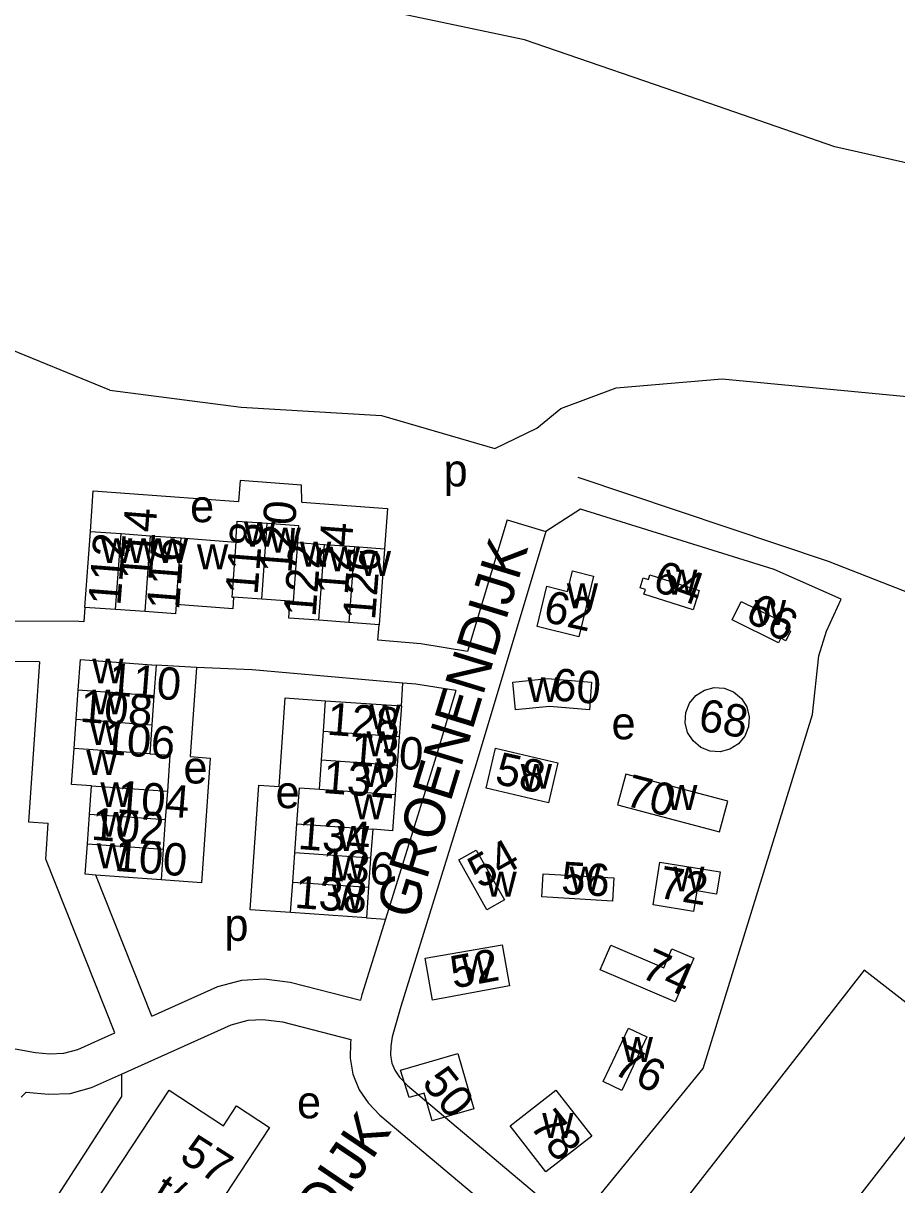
# Model space of a CAD drawing. Extents: x 159441 to 162086, y 388175 to 389787.
# Drawn here: x 160153.1 to 160261, y 389425.1 to 389568.6 of the extents above; entities that cross this region are included whole.
import ezdxf

# ---------------------------------------------------------------- set-up
doc = ezdxf.new("R2010")
doc.units = 0
for name, color, linetype in [('BLT_Basislijn', 7, 'Continuous'), ('BLT_Bebouwing', 7, 'Continuous'), ('BLT_Centroide', 7, 'Continuous'), ('BLT_Huisnummer', 7, 'Continuous'), ('BLT_Huisnummer_ tussenligend', 7, 'Continuous'), ('BLT_Huisnummer_zonder_bebouwing', 7, 'Continuous'), ('BLT_Onderverdeling_panden', 7, 'Continuous'), ('BLT_Plantopo', 7, 'Continuous'), ('BLT_Straatnaam', 7, 'Continuous')]:
    doc.layers.add(name, color=color, linetype=linetype)

msp = doc.modelspace()

# ---------------------------------------------------------------- linework, layer by layer
at = {"layer": 'BLT_Basislijn'}
for p, q in [((160163.8, 389523.25), (160141.73, 389532.25)), ((160212.87, 389507.2), (160207.99, 389490.96)), ((160212.87, 389507.2), (160217.66, 389505.76)), ((160174.51, 389489), (160169.52, 389489.28)), ((160174.51, 389489), (160173.72, 389477.98)), ((160199.8, 389484.24), (160200, 389487.06)), ((160155.87, 389465.33), (160156.18, 389469.75)), ((160164.41, 389443.88), (160155.87, 389465.33)), ((160168.97, 389445.93), (160162.04, 389463.35)), ((160195.5, 389458.06), (160197.84, 389457.9))]:
    msp.add_line(p, q, dxfattribs=at)
for points in [[(160371.16, 389573.06), (160363.22, 389567.72), (160358.94, 389565.1), (160350.1, 389560.99), (160341.38, 389557.76), (160340.2, 389558.69), (160327.39, 389554.65), (160307.62, 389550.59), (160288, 389549.69), (160272.71, 389550.9), (160270.1, 389550.9), (160268.89, 389549.78), (160253.35, 389553.3), (160237.78, 389558.66), (160215.01, 389566.48), (160191.12, 389571.55)], [(160163.8, 389523.25), (160180, 389521.15), (160197.35, 389520.11), (160211.37, 389516.04), (160216.55, 389518.54), (160219.5, 389520.97), (160226.34, 389523.51), (160239.42, 389524.63)], [(160239.42, 389524.63), (160266.58, 389522.05), (160272.05, 389521.43)], [(160187.5, 389509.4), (160187.46, 389511.52), (160187.46, 389511.52), (160179.89, 389512.06), (160179.7, 389509.47)], [(160268.48, 389495.85), (160268.48, 389495.85), (160252.56, 389502.07), (160221.63, 389512.44)], [(160161.38, 389505.79), (160161.74, 389510.79), (160179.7, 389509.47)], [(160187.5, 389509.4), (160198.09, 389508.62), (160197.73, 389503.63)], [(160252.31, 389493.46), (160252.31, 389493.46), (160254.16, 389497.44), (160245.85, 389501.09), (160221.95, 389508.55), (160217.66, 389505.76)], [(160217.66, 389505.76), (160209.05, 389477.09), (160199.72, 389447.12), (160198.67, 389443.39), (160198.5, 389442.22), (160198.48, 389441.1), (160198.63, 389440.12), (160198.99, 389439.26), (160199.59, 389438.41), (160200.58, 389437.37), (160221.21, 389420)], [(160160.69, 389496.41), (160160.56, 389494.64), (160159.96, 389494.67), (160145.91, 389494.71), (160136.49, 389494.39)], [(160207.99, 389490.96), (160202.22, 389491.89), (160196.91, 389492.35), (160197.05, 389494.26)], [(160221.21, 389420), (160237.09, 389439.47), (160250.58, 389483.19), (160251.38, 389490.44), (160252.31, 389493.46)], [(160155.11, 389489.68), (160145.98, 389489.71), (160136.48, 389489.38)], [(160155.11, 389489.68), (160153.72, 389469.93), (160156.18, 389469.75)], [(160200, 389487.06), (160181.35, 389488.69), (160174.51, 389489)], [(160206.54, 389486.13), (160201.6, 389486.92), (160200, 389487.06)], [(160184.69, 389474.29), (160185.45, 389485.22), (160190.44, 389484.88)], [(160206.54, 389486.13), (160204.26, 389478.55), (160197.84, 389457.9)], [(160173.72, 389477.98), (160176.2, 389477.8), (160175.1, 389462.41), (160170.11, 389462.77)], [(160186.12, 389458.71), (160181.13, 389459.05), (160182.21, 389474.46), (160184.69, 389474.29)], [(160197.84, 389457.9), (160194.93, 389448.54), (160194.74, 389447.89)], [(160241.32, 389404.38), (160270.16, 389441.35), (160257, 389451.61), (160228.13, 389414.61)], [(160168.97, 389445.93), (160177.12, 389449.6), (160180.1, 389450.38), (160182.86, 389450.55), (160186.06, 389450.13), (160194.74, 389447.89)], [(160165.21, 389438.76), (160178.79, 389444.87), (160180.89, 389445.41), (160182.69, 389445.53), (160185.11, 389445.21), (160193.56, 389443.03)], [(160151.2, 389442.05), (160154.59, 389441.45), (160156.33, 389441.28), (160158.12, 389441.35), (160159.83, 389441.82), (160164.41, 389443.88)], [(160193.56, 389443.03), (160193.5, 389442.63), (160193.47, 389440.74), (160193.79, 389438.75), (160194.58, 389436.84), (160195.71, 389435.23), (160197.16, 389433.71), (160218.41, 389415.82)], [(160165.21, 389438.76), (160165.21, 389436.02), (160151.05, 389414.07), (160139.58, 389381.2)], [(160152.84, 389435.93), (160153.45, 389436.54), (160156.19, 389436.27), (160158.9, 389436.38), (160161.53, 389437.1), (160165.21, 389438.76)]]:
    msp.add_lwpolyline(points, dxfattribs=at)
at = {"layer": 'BLT_Bebouwing'}
for p, q in [((160160.69, 389496.41), (160161.38, 389505.79)), ((160161.38, 389505.79), (160165.17, 389505.52)), ((160165.17, 389505.52), (160168.76, 389505.26)), ((160161.3, 389504.74), (160161.32, 389504.96)), ((160168.76, 389505.26), (160172.6, 389504.98)), ((160172.6, 389504.98), (160179.34, 389504.46)), ((160186.96, 389504.43), (160190.29, 389504.18)), ((160190.29, 389504.18), (160194.03, 389503.91)), ((160194.03, 389503.91), (160197.73, 389503.63)), ((160197.73, 389503.63), (160197.05, 389494.26)), ((160182.56, 389497.43), (160179.08, 389497.68)), ((160186.04, 389497.18), (160182.56, 389497.43)), ((160164.5, 389496.14), (160160.69, 389496.41)), ((160168.09, 389495.88), (160164.5, 389496.14)), ((160193.33, 389494.54), (160189.61, 389494.81)), ((160197.05, 389494.26), (160193.33, 389494.54)), ((160159.88, 389486.18), (160160.15, 389489.96)), ((160169.52, 389489.28), (160169.24, 389485.49)), ((160159.63, 389482.59), (160159.88, 389486.18)), ((160169.24, 389485.49), (160168.99, 389481.9)), ((160190.18, 389481.11), (160190.44, 389484.88)), ((160190.44, 389484.88), (160199.8, 389484.24)), ((160199.8, 389484.24), (160199.53, 389480.46)), ((160159.38, 389479), (160159.63, 389482.59)), ((160168.99, 389481.9), (160168.73, 389478.34)), ((160189.93, 389477.52), (160190.18, 389481.11)), ((160199.53, 389480.46), (160199.27, 389476.87)), ((160189.68, 389473.94), (160189.93, 389477.52)), ((160199.27, 389476.87), (160199.02, 389473.28)), ((160161.27, 389470.81), (160161.52, 389474.36)), ((160170.9, 389473.69), (160170.64, 389470.15)), ((160161.01, 389467.22), (160161.27, 389470.81)), ((160170.64, 389470.15), (160170.39, 389466.55)), ((160186.63, 389466.08), (160186.88, 389469.66)), ((160196.27, 389469.01), (160196.01, 389465.43)), ((160160.74, 389463.44), (160161.01, 389467.22)), ((160170.39, 389466.55), (160170.11, 389462.77)), ((160186.38, 389462.49), (160186.63, 389466.08)), ((160196.01, 389465.43), (160195.76, 389461.84)), ((160162.04, 389463.35), (160160.74, 389463.44)), ((160170.11, 389462.77), (160162.04, 389463.35)), ((160186.12, 389458.71), (160186.38, 389462.49)), ((160195.76, 389461.84), (160195.5, 389458.06)), ((160195.5, 389458.06), (160186.12, 389458.71))]:
    msp.add_line(p, q, dxfattribs=at)
for points in [[(160179.34, 389504.46), (160179.53, 389507.07), (160183.23, 389506.81)], [(160183.23, 389506.81), (160187.11, 389506.53), (160186.96, 389504.43)], [(160171.97, 389496.77), (160171.88, 389495.61), (160168.09, 389495.88)], [(160179.08, 389497.68), (160178.98, 389496.23), (160171.97, 389496.77)], [(160189.61, 389494.81), (160185.89, 389495.08), (160186.04, 389497.18)], [(160160.15, 389489.96), (160169.52, 389489.28)], [(160161.52, 389474.36), (160159.06, 389474.55), (160159.38, 389479)], [(160168.73, 389478.34), (160171.21, 389478.16), (160170.9, 389473.69)], [(160186.88, 389469.66), (160187.2, 389474.11), (160189.68, 389473.94)], [(160199.02, 389473.28), (160198.7, 389468.83), (160196.27, 389469.01)]]:
    msp.add_lwpolyline(points, dxfattribs=at)
for points in [[(160220.93, 389500.93), (160223.55, 389500.27), (160221.73, 389492.79), (160216.58, 389494.05), (160217.77, 389499.01), (160220.31, 389498.39)], [(160235.85, 389496.1), (160229.76, 389498.03), (160229.95, 389498.62), (160229.29, 389498.83), (160229.67, 389500.04), (160230.33, 389499.84), (160230.52, 389500.43), (160236.61, 389498.5)], [(160247.53, 389494.32), (160247.26, 389493.77), (160247.89, 389493.47), (160247.31, 389492.28), (160246.68, 389492.59), (160246.41, 389492.03), (160240.66, 389494.87), (160241.79, 389497.15)], [(160213.57, 389487.19), (160217.85, 389487.61), (160223.3, 389487.18), (160223.04, 389483.77), (160218.12, 389484.15), (160213.9, 389483.74)], [(160211.45, 389479.02), (160219.15, 389477.21), (160217.98, 389472.26), (160210.28, 389474.08)], [(160227.53, 389475.83), (160226.52, 389472.04), (160239.12, 389468.67), (160240.12, 389472.47)], [(160206.9, 389465.21), (160209.06, 389466.43), (160212.54, 389460.28), (160210.36, 389459.05)], [(160235.91, 389458.85), (160230.91, 389459.66), (160231.75, 389464.94), (160239.18, 389463.75), (160238.75, 389461.01), (160236.32, 389461.4)], [(160225.88, 389460.14), (160217.15, 389460.66), (160217.33, 389463.5), (160226.06, 389462.99)], [(160203.67, 389447.9), (160202.76, 389453.09), (160212.26, 389454.75), (160213.16, 389449.65)], [(160227.85, 389444.45), (160230.14, 389443.36), (160227.04, 389436.75), (160224.74, 389437.84)], [(160223.33, 389431.12), (160217.67, 389426.68), (160213.24, 389432.36), (160218.9, 389436.78)]]:
    msp.add_lwpolyline(points, close=True, dxfattribs=at)
at = {"layer": 'BLT_Onderverdeling_panden'}
for p, q in [((160182.56, 389497.43), (160183.23, 389506.81)), ((160164.5, 389496.14), (160165.17, 389505.52)), ((160168.76, 389505.26), (160168.09, 389495.88)), ((160171.97, 389496.77), (160172.6, 389504.98)), ((160189.61, 389494.81), (160190.29, 389504.18)), ((160194.03, 389503.91), (160193.33, 389494.54)), ((160169.24, 389485.49), (160159.88, 389486.18)), ((160159.63, 389482.59), (160168.99, 389481.9)), ((160190.18, 389481.11), (160199.53, 389480.46)), ((160168.73, 389478.34), (160159.38, 389479)), ((160199.27, 389476.87), (160189.93, 389477.52)), ((160161.52, 389474.36), (160170.9, 389473.69)), ((160189.68, 389473.94), (160199.02, 389473.28)), ((160170.64, 389470.15), (160161.27, 389470.81)), ((160186.88, 389469.66), (160196.27, 389469.01)), ((160161.01, 389467.22), (160170.39, 389466.55)), ((160196.01, 389465.43), (160186.63, 389466.08)), ((160186.38, 389462.49), (160195.76, 389461.84))]:
    msp.add_line(p, q, dxfattribs=at)
for points in [[(160179.34, 389504.46), (160178.85, 389497.69), (160179.08, 389497.68)], [(160186.96, 389504.43), (160186.44, 389497.15), (160186.04, 389497.18)]]:
    msp.add_lwpolyline(points, dxfattribs=at)
at = {"layer": 'BLT_Plantopo'}
for points in [[(160235.4, 389484.57), (160236.19, 389485.53), (160237.24, 389486.19), (160238.45, 389486.5), (160239.69, 389486.42), (160240.85, 389485.96), (160241.81, 389485.17), (160242.48, 389484.12), (160242.79, 389482.91), (160242.71, 389481.67), (160242.25, 389480.51), (160241.45, 389479.55), (160240.4, 389478.88), (160239.2, 389478.57), (160237.95, 389478.65), (160236.79, 389479.11), (160235.84, 389479.91), (160235.17, 389480.96), (160234.86, 389482.16), (160234.94, 389483.41)], [(160225.69, 389454.71), (160232.25, 389451.91), (160233.23, 389454.22), (160235.93, 389453.07), (160233.64, 389447.7), (160224.38, 389451.65)], [(160199.68, 389439.25), (160206.78, 389441.32), (160208.77, 389434.49), (160203.62, 389432.99), (160202.62, 389436.41), (160200.76, 389435.87)], [(160171.11, 389436.8), (160177.84, 389432.38), (160179.45, 389434.83), (160183.5, 389432.17), (160170.03, 389411.69), (160172.89, 389409.81), (160160.9, 389391.58), (160164.73, 389389.06), (160160.78, 389383.06), (160147.45, 389391.83), (160151.15, 389397.46), (160150.07, 389398.17), (160158.03, 389410.28), (160154.98, 389412.29)]]:
    msp.add_lwpolyline(points, close=True, dxfattribs=at)

# ---------------------------------------------------------------- texts
at = {"layer": 'BLT_Centroide'}
for s, p in [('p', (160205.02, 389511.35)), ('e', (160173.7, 389506.93)), ('w', (160180.36, 389503.89)), ('w', (160183.52, 389503.18)), ('w', (160162.7, 389501.88)), ('w', (160166.02, 389501.88)), ('w', (160169.6, 389501.88)), ('w', (160174.55, 389501.12)), ('w', (160187.27, 389501.44)), ('w', (160190.85, 389500.84)), ('w', (160194.66, 389500.3)), ('w', (160232.51, 389497.99)), ('w', (160220.24, 389496.31)), ('w', (160243.47, 389494.23)), ('w', (160161.61, 389487.01)), ('w', (160215.39, 389484.71)), ('w', (160161.61, 389483.18)), ('w', (160195.85, 389481.34)), ('w', (160161.31, 389479.4)), ('e', (160225.77, 389480.12)), ('w', (160195.51, 389478.01)), ('w', (160160.87, 389475.71)), ('e', (160172.88, 389474.66)), ('w', (160194.92, 389474.22)), ('w', (160214.55, 389474)), ('w', (160162.61, 389471.75)), ('e', (160184.26, 389471.61)), ('w', (160232.51, 389471.38)), ('w', (160193.9, 389470.25)), ('w', (160162.61, 389468.08)), ('w', (160191.95, 389466.32)), ('w', (160162.17, 389464.2)), ('w', (160191.54, 389462.68)), ('w', (160210.19, 389460.68)), ('w', (160220.56, 389461.33)), ('w', (160233.39, 389461.33)), ('w', (160191.27, 389458.99)), ('p', (160177.94, 389455.23)), ('w', (160207.28, 389450.29)), ('w', (160227.02, 389440.27)), ('e', (160186.91, 389433.31)), ('w', (160217.21, 389430.88))]:
    msp.add_text(s, height=4, dxfattribs=at).set_placement(p)
at = {"layer": 'BLT_Huisnummer'}
for s, rotation, p in [('118', 85.5267, (160182.03, 389497.88)), ('112', 85.5267, (160165.09, 389496.55)), ('116', 85.5267, (160172.32, 389496.02)), ('122', 85.5267, (160189.2, 389495.15)), ('126', 85.5267, (160196.55, 389494.77)), ('62', 347.5267, (160217.19, 389494.69)), ('110', 355.5267, (160163.53, 389485.59)), ('60', 355.5267, (160218.35, 389484.93)), ('128', 355.5267, (160190.53, 389480.7)), ('68', 350.5267, (160236.37, 389481.22)), ('106', 355.5267, (160162.8, 389478.33)), ('58', 347.5267, (160211.21, 389474.68)), ('132', 355.5267, (160190.01, 389473.5)), ('70', 345.5267, (160227.27, 389471.97)), ('104', 355.5267, (160164.57, 389471.06)), ('134', 355.5267, (160186.95, 389466.58)), ('100', 355.5267, (160164.28, 389463.88)), ('54', 29.5267, (160209.52, 389461.59)), ('56', 356.5267, (160219.48, 389461.04)), ('72', 350.5267, (160231.43, 389460.57)), ('138', 355.5267, (160186.52, 389459.31)), ('74', 335.5267, (160229.19, 389450.81))]:
    msp.add_text(s, height=4, rotation=rotation, dxfattribs=at).set_placement(p)
at = {"layer": 'BLT_Huisnummer_ tussenligend'}
for s, rotation, p in [('114', 85.5267, (160168.94, 389499.66)), ('120', 85.5267, (160186.21, 389500.54)), ('124', 85.5267, (160193.19, 389497.87)), ('108', 355.5267, (160160, 389482.29)), ('130', 355.5267, (160193.45, 389476.97)), ('102', 355.5267, (160161.41, 389467.72)), ('136', 355.5267, (160189.84, 389462.76))]:
    msp.add_text(s, height=4, rotation=rotation, dxfattribs=at).set_placement(p)
at = {"layer": 'BLT_Huisnummer_zonder_bebouwing'}
for s, rotation, p in [('64', 340.5267, (160230.66, 389498.58)), ('66', 330.5267, (160242.06, 389494.94)), ('52', 10.5267, (160206.26, 389449.32)), ('76', 334.5267, (160225.77, 389438.89)), ('50', 308.5267, (160202.22, 389437.67)), ('78', 308.5267, (160215.54, 389432.36)), ('57', 327.5267, (160172.22, 389428.16)), ('t/m', 327.5267, (160168.7, 389423.29))]:
    msp.add_text(s, height=4, rotation=rotation, dxfattribs=at).set_placement(p)
at = {"layer": 'BLT_Straatnaam'}
for rotation, p in [(73.0004, (160201.4, 389457.68)), (56.0004, (160171.65, 389391.72))]:
    msp.add_text('GROENENDIJK', height=5, rotation=rotation, dxfattribs=at).set_placement(p)

doc.saveas('drawing.dxf')
